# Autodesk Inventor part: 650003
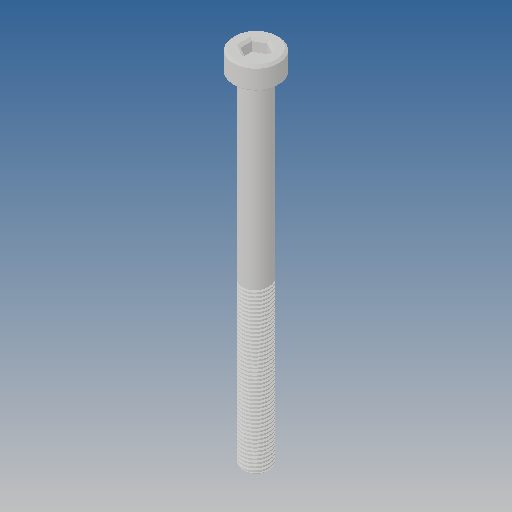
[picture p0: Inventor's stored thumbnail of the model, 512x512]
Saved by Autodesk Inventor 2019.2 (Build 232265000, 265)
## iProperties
Created: 2013-07
Part Number: 650003
Material: Ogólny
Document SubType Name: Modeling
Designer: CADENGINEERING4
Density: 1 g/cm^3
Appearance: Domyślna
Author: CADENGINEERING4
Revision Number: ÈÎºÎ
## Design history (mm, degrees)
feature "ÇÐ³ý-É¨Ãè1"
node "Bryła1"
